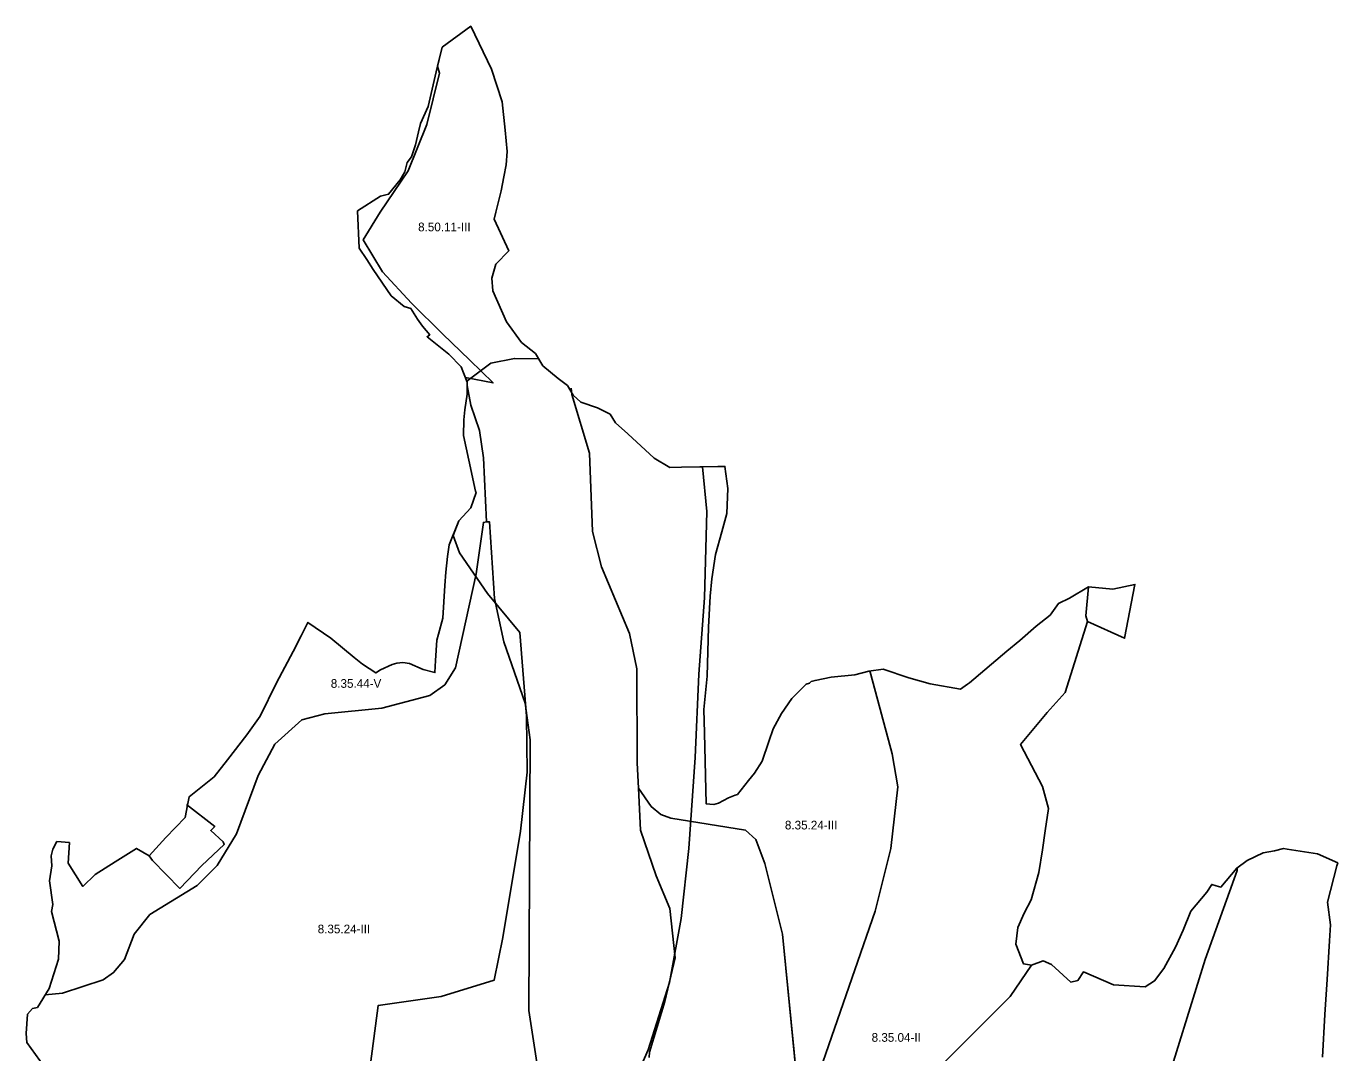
# Model space of a CAD drawing. Extents: x -547623 to -533936, y -1096714 to -1086523.
# Drawn here: x -540625 to -539120, y -1091678 to -1090500 of the extents above; entities that cross this region are included whole.
import ezdxf

# ---------------------------------------------------------------- set-up
doc = ezdxf.new("R2010")
doc.units = 0
for name, color, linetype in [('Vrstva 27', 7, 'Continuous'), ('Vrstva 28', 7, 'Continuous'), ('Vrstva 29', 7, 'Continuous')]:
    doc.layers.add(name, color=color, linetype=linetype)

msp = doc.modelspace()

# ---------------------------------------------------------------- linework, layer by layer
at = {"layer": 'Vrstva 28'}
for p, q in [((-540037.1, -1090881.3), (-540037.1, -1090881.3)), ((-539920.5, -1091422), (-539922.5, -1091374)), ((-539922.5, -1091374), (-539908, -1091395)), ((-539908, -1091395), (-539897, -1091404)), ((-539897, -1091404), (-539885.5, -1091408.5)), ((-539885.5, -1091408.5), (-539800, -1091422)), ((-539902.5, -1091474.5), (-539920.5, -1091422)), ((-539800, -1091422), (-539788, -1091433)), ((-539788, -1091433), (-539777.5, -1091460.5)), ((-539777.5, -1091460.5), (-539757.5, -1091541.5)), ((-539886.5, -1091512), (-539902.5, -1091474.5)), ((-539880.5, -1091568.5), (-539886.5, -1091512)), ((-539757.5, -1091541.5), (-539737.5, -1091744)), ((-539892.5, -1091618.5), (-539880.5, -1091568.5)), ((-539910, -1091677), (-539892.5, -1091618.5)), ((-539910.5, -1091683), (-539910, -1091677))]:
    msp.add_line(p, q, dxfattribs=at)
for points in [[(-539137.7, -1091682.6), (-539134.9, -1091633.7), (-539132.2, -1091593.3), (-539129.8, -1091549), (-539128.5, -1091530.6), (-539132, -1091504.6), (-539121.2, -1091463.1), (-539120.2, -1091459.7), (-539143.6, -1091449.3), (-539178.2, -1091443.9), (-539182.6, -1091443.3), (-539192.7, -1091445.7), (-539205.9, -1091448.2), (-539224.2, -1091456.8), (-539236.2, -1091465.9), (-539254.3, -1091487.4), (-539259.8, -1091485.8), (-539264.8, -1091484.3), (-539270.6, -1091493.1), (-539289, -1091514.9), (-539297.7, -1091536.7), (-539306.4, -1091556.5), (-539319.8, -1091580.7), (-539330.5, -1091595.1), (-539341.3, -1091601.7), (-539377.7, -1091599.7), (-539412, -1091584.8), (-539418.4, -1091594.5), (-539426.7, -1091596.4), (-539448.7, -1091576.3), (-539458.4, -1091572), (-539471.7, -1091576.9), (-539481, -1091575.3), (-539489.6, -1091553.1), (-539487.2, -1091533.7), (-539480.1, -1091517.3), (-539472, -1091502), (-539463.2, -1091470.8), (-539459.2, -1091444.8), (-539456, -1091423), (-539452.1, -1091397.2), (-539459.2, -1091372.2), (-539484.2, -1091323.7), (-539453.6, -1091287.2), (-539433, -1091264.2), (-539407.4, -1091182.8), (-539364.8, -1091201.9), (-539352.9, -1091140.1), (-539378.2, -1091145.5), (-539406.1, -1091142.9), (-539428.1, -1091155.8), (-539440.7, -1091162), (-539450.1, -1091175.3), (-539466.2, -1091187.9), (-539484.9, -1091204.5), (-539499.8, -1091216.8), (-539542.7, -1091253.1), (-539545.1, -1091254.7), (-539553, -1091260.3), (-539587.9, -1091254.1), (-539612.3, -1091247.5), (-539641.7, -1091237.3), (-539658.3, -1091239.6), (-539674.5, -1091243.9), (-539701.4, -1091246.6), (-539720, -1091250.4), (-539724.4, -1091251.5), (-539726.2, -1091253.3), (-539730.1, -1091254.5), (-539746.8, -1091271), (-539758.7, -1091288.3), (-539768, -1091305.9), (-539773.2, -1091320.5), (-539780.6, -1091342.8), (-539789.6, -1091356.6), (-539796.4, -1091365.2), (-539809.1, -1091381.2), (-539811.5, -1091382.1), (-539819.5, -1091385.2), (-539830.9, -1091391.1), (-539836.2, -1091392.5), (-539840.7, -1091392.3), (-539844.9, -1091392.1), (-539847, -1091310.3), (-539847.8, -1091283.8), (-539844, -1091245.4), (-539842.2, -1091189.1), (-539840.2, -1091153.5), (-539838.5, -1091133.6), (-539834.3, -1091106), (-539826.9, -1091079.9), (-539821.1, -1091058.9), (-539820.2, -1091030.1), (-539823.4, -1091004.8), (-539831.6, -1091004.9), (-539873.2, -1091005.7), (-539886.7, -1091005.9), (-539904.8, -1090995.4), (-539934.9, -1090967.5), (-539949.1, -1090955), (-539955.3, -1090944.7), (-539969.5, -1090937.5), (-539988.7, -1090931.1), (-539997.6, -1090923.1), (-540004.2, -1090912), (-540014.9, -1090904), (-540032.2, -1090889.4), (-540040.9, -1090875.2), (-540056.7, -1090862.6), (-540074.2, -1090839), (-540089.8, -1090803.2), (-540091, -1090788.8), (-540086.2, -1090772.6), (-540071.4, -1090757.5), (-540088.3, -1090721.2), (-540086.3, -1090713), (-540080.3, -1090688.7), (-540077.1, -1090672.5), (-540074.4, -1090658.9), (-540073.2, -1090643.6), (-540075.6, -1090619.1), (-540079.2, -1090586.5), (-540091.2, -1090549.2), (-540115.1, -1090499.8), (-540147.9, -1090524), (-540154.6, -1090552.3), (-540163.8, -1090591.8), (-540172.9, -1090611.3), (-540174.9, -1090620.8), (-540178.6, -1090636), (-540183.2, -1090649.8), (-540187.9, -1090656.1), (-540190.9, -1090666.9), (-540195.9, -1090676.1), (-540209.4, -1090692.6), (-540218.7, -1090694.7), (-540244.9, -1090711.7), (-540243.3, -1090754.4), (-540234.3, -1090767.6), (-540227.1, -1090779), (-540206.3, -1090809.2), (-540191.6, -1090821.5), (-540183.9, -1090823.6), (-540176.3, -1090835.8), (-540170.5, -1090844.1), (-540162.2, -1090853.8), (-540165.2, -1090856.1), (-540140.1, -1090876.2), (-540126, -1090890.4), (-540123.3, -1090897.3), (-540119.1, -1090908.1), (-540119.2, -1090921.8), (-540121.7, -1090939.9), (-540122.9, -1090951.2), (-540123.6, -1090969.4), (-540117.3, -1090997.5), (-540109.8, -1091033.1), (-540108.8, -1091034.7), (-540115.1, -1091052.4), (-540128.6, -1091067.4), (-540139.8, -1091094.6), (-540141.6, -1091108), (-540143.7, -1091126.1), (-540144.9, -1091141.3), (-540147, -1091178.9), (-540152.2, -1091197.2), (-540153.9, -1091204.2), (-540155.6, -1091227.6), (-540156.3, -1091241.3), (-540157.8, -1091240.9), (-540169.7, -1091237.9), (-540185.2, -1091231), (-540192.9, -1091229.9), (-540199.9, -1091230.4), (-540205.4, -1091232.1), (-540218.8, -1091238), (-540224.2, -1091241.8), (-540239.2, -1091231.7), (-540249, -1091224.1), (-540262.4, -1091212.8), (-540275.7, -1091201.9), (-540302, -1091183.8), (-540309.6, -1091199), (-540318.7, -1091217.1), (-540338, -1091253), (-540356.9, -1091291.5), (-540372, -1091312.8), (-540394.4, -1091341.3), (-540409.7, -1091360.8), (-540438.2, -1091383.8), (-540440.1, -1091393.3), (-540442.8, -1091407.6), (-540464.8, -1091430.7), (-540484.1, -1091451.4), (-540498.8, -1091443.1), (-540523.2, -1091458.6), (-540534.7, -1091465.9), (-540545.9, -1091473), (-540560.2, -1091486.6), (-540577.2, -1091459.9), (-540575.7, -1091436.4), (-540590, -1091435.3), (-540594.5, -1091444), (-540596.7, -1091451.5), (-540595.9, -1091462.9), (-540598.3, -1091480.1), (-540594.6, -1091507.5), (-540596.2, -1091515.3), (-540587.4, -1091549.3), (-540588.2, -1091570), (-540598.8, -1091603.6), (-540612.3, -1091625.4), (-540617.8, -1091626.6), (-540623.7, -1091633.3), (-540625.2, -1091655.3), (-540624.5, -1091665.9), (-540594.5, -1091707)], [(-540037.1, -1090881.3), (-540037.1, -1090881.3), (-540065, -1090881), (-540092, -1090886.5), (-540119.5, -1090907.1)], [(-540119.5, -1090907.1), (-540092, -1090886.5), (-540065, -1090881), (-540037.1, -1090881.3), (-540037.1, -1090881.3)], [(-540119.1, -1090912.1), (-540115, -1090934.5), (-540105, -1090963.5), (-540100.5, -1090995), (-540097, -1091068.5), (-540100.5, -1091069), (-540109, -1091128), (-540132.5, -1091236), (-540145, -1091255.5), (-540162, -1091267.5), (-540217, -1091282), (-540282.5, -1091288.5), (-540309, -1091295.5), (-540340, -1091323.5), (-540359, -1091359.5), (-540384, -1091426.5), (-540406, -1091462.5), (-540429, -1091485.5), (-540483.5, -1091519), (-540501.5, -1091541.5), (-540512.5, -1091570.5), (-540525, -1091585.5), (-540537, -1091594), (-540583.5, -1091609), (-540603.5, -1091611.2)], [(-540119.1, -1090912.1), (-540119.1, -1090908.1), (-540119.5, -1090907.1)], [(-540030.5, -1091746), (-540048.5, -1091629), (-540047, -1091318.5), (-540052.5, -1091276.5), (-540077, -1091206), (-540088, -1091156.5), (-540093.5, -1091068.5), (-540097, -1091068.5), (-540100.5, -1090995), (-540105, -1090963.5), (-540115, -1090934.5), (-540119.1, -1090912.1)], [(-539737.5, -1091744), (-539757.5, -1091541.5), (-539777.5, -1091460.5), (-539788, -1091433), (-539800, -1091422), (-539885.5, -1091408.5), (-539897, -1091404), (-539908, -1091395), (-539922.5, -1091374), (-539924, -1091345), (-539924.5, -1091237), (-539933, -1091196.5), (-539965, -1091120), (-539975.5, -1091079.5), (-539979, -1090989.5), (-539999, -1090922.5), (-540000, -1090915.1)], [(-540603.5, -1091611.2), (-540583.5, -1091609), (-540537, -1091594), (-540525, -1091585.5), (-540512.5, -1091570.5), (-540501.5, -1091541.5), (-540483.5, -1091519), (-540429, -1091485.5), (-540406, -1091462.5), (-540384, -1091426.5), (-540359, -1091359.5), (-540340, -1091323.5), (-540309, -1091295.5), (-540282.5, -1091288.5), (-540217, -1091282), (-540162, -1091267.5), (-540145, -1091255.5), (-540132.5, -1091236), (-540109, -1091128), (-540100.5, -1091069), (-540097, -1091068.5), (-540093.5, -1091068.5), (-540088, -1091156.5), (-540077, -1091206), (-540052.5, -1091276.5), (-540047, -1091318.5), (-540048.5, -1091629), (-540030.5, -1091746)], [(-539406.1, -1091142.9), (-539409.3, -1091176.1), (-539407.4, -1091182.8), (-539364.8, -1091201.9), (-539352.9, -1091140.1), (-539378.2, -1091145.5), (-539406.1, -1091142.9)], [(-539169.5, -1092577), (-539185.5, -1092571), (-539287, -1092514.5), (-539311.5, -1092507), (-539332, -1092498.5), (-539347, -1092488.5), (-539393.5, -1092439), (-539531, -1092243), (-539596, -1092117.5), (-539651, -1091998.5), (-539660.5, -1091976.5), (-539710, -1091856), (-539731, -1091782), (-539729.5, -1091762), (-539721, -1091717), (-539651, -1091515), (-539633, -1091443), (-539625, -1091372.5), (-539631.5, -1091334.5), (-539656, -1091243.5), (-539657, -1091239.4)], [(-539657, -1091239.4), (-539656, -1091243.5), (-539631.5, -1091334.5), (-539625, -1091372.5), (-539633, -1091443), (-539651, -1091515), (-539721, -1091717)], [(-540441.3, -1091392.6), (-540408.9, -1091417.9), (-540413.5, -1091422.4), (-540399, -1091435.5), (-540398, -1091438.5), (-540423.5, -1091462.5), (-540449, -1091489), (-540480.2, -1091457.1), (-540484.1, -1091451.4)], [(-539235.5, -1091465), (-539235.5, -1091468.5), (-539272.5, -1091570.5), (-539322.5, -1091732), (-539327.5, -1091777), (-539322, -1091808.5), (-539304.5, -1091844.5), (-539210.5, -1091966), (-539203, -1091981.5), (-539198.5, -1092000), (-539183, -1092021.8)], [(-539471.7, -1091576.9), (-539496, -1091613), (-539580.5, -1091697.5), (-539607, -1091738), (-539623.5, -1091778), (-539629, -1091819), (-539622, -1091864), (-539604, -1091913.5), (-539567.5, -1091999), (-539534, -1092042), (-539516.5, -1092057.5), (-539451, -1092092.5), (-539425, -1092116), (-539392.5, -1092161), (-539341, -1092251), (-539328.5, -1092269), (-539309, -1092291.5), (-539261.5, -1092325.3)]]:
    msp.add_lwpolyline(points, dxfattribs=at)
at = {"layer": 'Vrstva 29'}
for points in [[(-539937.2, -1091732.2), (-539911.5, -1091674.3), (-539887.1, -1091596.8), (-539873.5, -1091523.5), (-539864.7, -1091443.3), (-539857.4, -1091338.6), (-539853.4, -1091243.3), (-539846.8, -1091155.4), (-539844.2, -1091056.5), (-539849, -1091005.3), (-539873.2, -1091005.7), (-539886.7, -1091005.9), (-539904.8, -1090995.4), (-539934.9, -1090967.5), (-539949.1, -1090955), (-539955.3, -1090944.7), (-539969.5, -1090937.5), (-539988.7, -1090931.1), (-539997.6, -1090923.1), (-540004.2, -1090912), (-540014.9, -1090904), (-540032.2, -1090889.4), (-540040.9, -1090875.2), (-540056.7, -1090862.6), (-540074.2, -1090839), (-540089.8, -1090803.2), (-540091, -1090788.8), (-540086.2, -1090772.6), (-540071.4, -1090757.5), (-540088.3, -1090721.2), (-540086.3, -1090713), (-540080.3, -1090688.7), (-540077.1, -1090672.5), (-540074.4, -1090658.9), (-540073.2, -1090643.6), (-540075.6, -1090619.1), (-540079.2, -1090586.5), (-540091.2, -1090549.2), (-540115.1, -1090499.8), (-540147.9, -1090524), (-540153.1, -1090545.8)], [(-540153.1, -1090545.8), (-540151, -1090553.5), (-540165.4, -1090612.6), (-540186.8, -1090665.8), (-540219.1, -1090713.3), (-540238.4, -1090744.7), (-540216.3, -1090781.7), (-540182.9, -1090817.6), (-540147.6, -1090852.7), (-540116.1, -1090883), (-540089.5, -1090909), (-540121.2, -1090902.9), (-540119.1, -1090908.1), (-540119.2, -1090921.8), (-540121.7, -1090939.9), (-540122.9, -1090951.2), (-540123.6, -1090969.4), (-540117.3, -1090997.5), (-540109.8, -1091033.1), (-540108.8, -1091034.7), (-540115.1, -1091052.4), (-540128.6, -1091067.4), (-540135.4, -1091083.9), (-540127.9, -1091104), (-540095.9, -1091150.8), (-540058.8, -1091195.3), (-540051.1, -1091291.4), (-540050.2, -1091355.5), (-540058.1, -1091423.3), (-540078.1, -1091545.3), (-540088.3, -1091594.4), (-540149.2, -1091612.8), (-540221.2, -1091623.2), (-540230.3, -1091690.3)]]:
    msp.add_lwpolyline(points, dxfattribs=at)

# ---------------------------------------------------------------- texts
at = {"layer": 'Vrstva 27'}
for s, p in [('8.50.11-III', (-540175.5, -1090735.1)), ('8.35.44-V', (-540275.7, -1091258.8)), ('8.35.24-III', (-539754.6, -1091421.3)), ('8.35.24-III', (-540290.7, -1091540.5)), ('8.35.04-II', (-539655.1, -1091664.9))]:
    msp.add_text(s, height=10, dxfattribs=at).set_placement(p)

doc.saveas('drawing.dxf')
